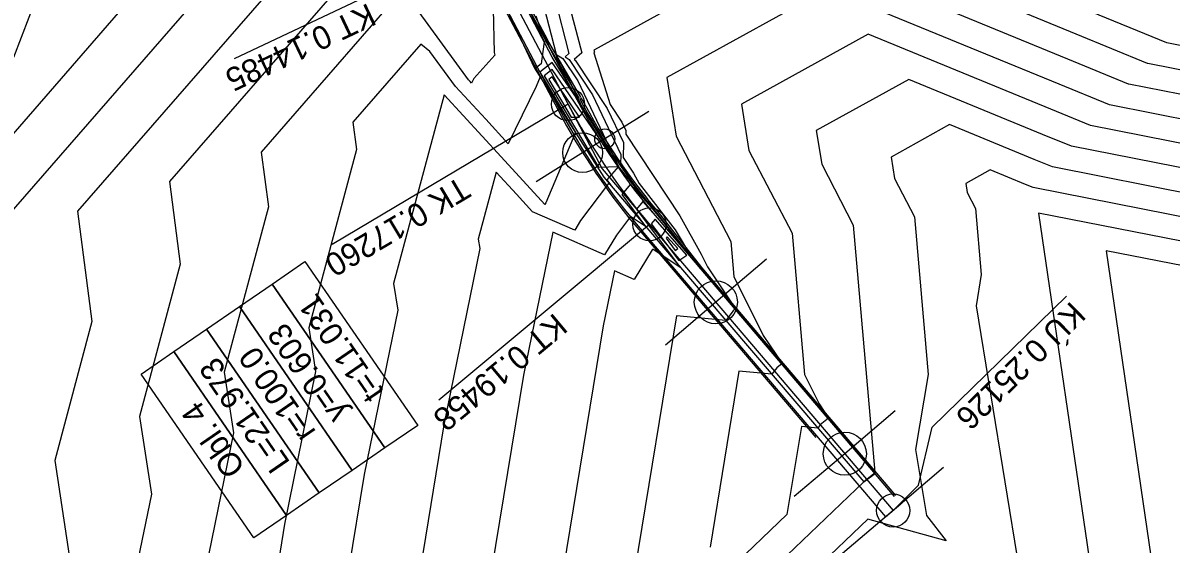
# Model space of a CAD drawing. Extents: x -549394 to -546608, y -1037055 to -1033629.
# Drawn here: x -547510.8 to -547337.6, y -1036070.9 to -1035992.3 of the extents above; entities that cross this region are included whole.
import ezdxf

# ---------------------------------------------------------------- set-up
doc = ezdxf.new("R2010")
doc.units = 0
for name, color, linetype in [('hlavni_vrst', 7, 'Continuous'), ('hrana_L', 7, 'Continuous'), ('norm_vrst', 7, 'Continuous'), ('POLYGONY_SITUACE_PO', 7, 'Continuous'), ('u_sirka_1_5m', 7, 'Continuous'), ('x_navrh_C41', 7, 'Continuous'), ('x_osa_C41', 7, 'Continuous'), ('x_popis_oblouky_C41', 7, 'Continuous'), ('x_popis_pricne_rezy_C41', 7, 'Continuous')]:
    doc.layers.add(name, color=color, linetype=linetype)

msp = doc.modelspace()

# ---------------------------------------------------------------- linework, layer by layer
at = {"layer": 'hlavni_vrst'}
for p, q in [((-547457.55, -1035980.45), (-547488.68, -1036016.25)), ((-547432.72, -1035980.4), (-547428.42, -1035996.91)), ((-547338.28, -1035995.31), (-547350.68, -1035990.21)), ((-547338.27, -1035995.32), (-547338.28, -1035995.31)), ((-547253.9, -1036011.93), (-547338.27, -1035995.32)), ((-547428.42, -1035996.91), (-547429.01, -1035997.44)), ((-547429.01, -1035997.44), (-547428.4, -1035997.81)), ((-547428.4, -1035997.81), (-547424.88, -1036003.14)), ((-547430.97, -1036000.44), (-547431.46, -1036000.82)), ((-547431.46, -1036000.82), (-547428.07, -1036006.54)), ((-547426.82, -1036006.5), (-547430.97, -1036000.44)), ((-547377.16, -1036000.82), (-547391.13, -1036008.54)), ((-547357.02, -1036009.12), (-547377.16, -1036000.82)), ((-547424.88, -1036003.14), (-547420.59, -1036012.16)), ((-547428.07, -1036006.54), (-547426.82, -1036006.5)), ((-547391.13, -1036008.54), (-547390.31, -1036013.64)), ((-547352.65, -1036010.91), (-547357.02, -1036009.12)), ((-547352.65, -1036010.92), (-547352.65, -1036010.91)), ((-547248.01, -1036031.52), (-547352.65, -1036010.92)), ((-547420.59, -1036012.16), (-547420.63, -1036013.66)), ((-547420.63, -1036013.66), (-547416.7, -1036018.73)), ((-547390.31, -1036013.64), (-547385.56, -1036022.8)), ((-547488.68, -1036016.25), (-547487.05, -1036028.71)), ((-547419.13, -1036016.61), (-547420.47, -1036018.2)), ((-547415.54, -1036020.67), (-547419.13, -1036016.61)), ((-547420.47, -1036018.2), (-547416.86, -1036023)), ((-547416.7, -1036018.73), (-547415.54, -1036020.67)), ((-547419.13, -1036021.5), (-547421.27, -1036024.34)), ((-547416.86, -1036023), (-547419.13, -1036021.5)), ((-547430.88, -1036023.9), (-547435.28, -1036045.47)), ((-547423.07, -1036027.31), (-547430.88, -1036023.9)), ((-547385.56, -1036022.8), (-547382.3, -1036060.1)), ((-547421.27, -1036024.34), (-547423.07, -1036027.31)), ((-547487.05, -1036028.71), (-547493.18, -1036051.67)), ((-547435.28, -1036045.47), (-547441.94, -1036086.16)), ((-547493.18, -1036051.67), (-547491.39, -1036063.41)), ((-547382.26, -1036060.17), (-547383.95, -1036061.55)), ((-547382.3, -1036060.1), (-547382.27, -1036060.15)), ((-547382.27, -1036060.15), (-547382.26, -1036060.17)), ((-547383.95, -1036061.55), (-547529.34, -1036200.56)), ((-547383.95, -1036061.55), (-547383.95, -1036061.55)), ((-547383.95, -1036061.55), (-547383.95, -1036061.55)), ((-547383.95, -1036061.55), (-547383.95, -1036061.55)), ((-547383.95, -1036061.55), (-547383.95, -1036061.55)), ((-547383.95, -1036061.55), (-547383.95, -1036061.55)), ((-547383.95, -1036061.55), (-547383.95, -1036061.55)), ((-547383.95, -1036061.55), (-547383.95, -1036061.55)), ((-547491.39, -1036063.41), (-547495.36, -1036082.87))]:
    msp.add_line(p, q, dxfattribs=at)
at = {"layer": 'hrana_L'}
for p, q in [((-547443.92, -1035977.28), (-547433.62, -1035999.11)), ((-547430.95, -1035997.46), (-547441.95, -1035976.42)), ((-547420.97, -1036013.96), (-547430.95, -1035997.46)), ((-547433.62, -1035999.11), (-547423.14, -1036015.56)), ((-547409.46, -1036028.18), (-547420.97, -1036013.96)), ((-547423.14, -1036015.56), (-547411.32, -1036029.57)), ((-547382.19, -1036060.25), (-547409.46, -1036028.18)), ((-547411.32, -1036029.57), (-547383.95, -1036061.55)), ((-547383.95, -1036061.55), (-547382.19, -1036060.25))]:
    msp.add_line(p, q, dxfattribs=at)
at = {"layer": 'norm_vrst'}
for p, q in [((-547497.77, -1035960.08), (-547512.2, -1035997.51)), ((-547460.95, -1035972.91), (-547502.52, -1036020.73)), ((-547436.76, -1035972.39), (-547430.35, -1035997)), ((-547351.95, -1035993.99), (-547401.7, -1035973.51)), ((-547477.28, -1035980.25), (-547516.37, -1036025.2)), ((-547395.57, -1035980.34), (-547424.56, -1035996.36)), ((-547353.22, -1035997.77), (-547395.57, -1035980.34)), ((-547435.78, -1035987.5), (-547432.13, -1035995.21)), ((-547389.43, -1035987.17), (-547413.67, -1036000.56)), ((-547354.49, -1036001.55), (-547389.43, -1035987.17)), ((-547494.74, -1035988.88), (-547530.21, -1036029.67)), ((-547454.15, -1035987.99), (-547474.83, -1036011.78)), ((-547428.69, -1035988.4), (-547426.49, -1035996.82)), ((-547443.56, -1036000.88), (-547451.39, -1035990.15)), ((-547439.87, -1035990.21), (-547439.71, -1035996.78)), ((-547433.43, -1035991.22), (-547433.03, -1035992.43)), ((-547433.03, -1035992.43), (-547430.74, -1035997.26)), ((-547383.29, -1035993.99), (-547402.4, -1036004.55)), ((-547355.75, -1036005.34), (-547383.29, -1035993.99)), ((-547341.16, -1035998.43), (-547351.95, -1035993.99)), ((-547450.75, -1035995.53), (-547460.99, -1036007.3)), ((-547449.39, -1035996.6), (-547450.75, -1035995.53)), ((-547432.2, -1035995.52), (-547432.63, -1035998.5)), ((-547432.13, -1035995.21), (-547432.2, -1035995.52)), ((-547424.56, -1035996.36), (-547424.65, -1035996.41)), ((-547424.65, -1035996.41), (-547424.57, -1035996.73)), ((-547445.51, -1036001.91), (-547449.39, -1035996.6)), ((-547439.62, -1035997.19), (-547442.79, -1036000.71)), ((-547439.71, -1035996.78), (-547439.62, -1035997.19)), ((-547430.74, -1035997.26), (-547430.27, -1035997.55)), ((-547430.35, -1035997), (-547430.38, -1035997.04)), ((-547430.38, -1035997.04), (-547429.33, -1035997.68)), ((-547430.27, -1035997.55), (-547429.33, -1035998.98)), ((-547429.33, -1035997.68), (-547427.1, -1036001.06)), ((-547426.49, -1035996.82), (-547427.63, -1035997.83)), ((-547427.63, -1035997.83), (-547427.47, -1035997.93)), ((-547427.47, -1035997.93), (-547422.66, -1036005.22)), ((-547424.57, -1035996.73), (-547424.65, -1035996.8)), ((-547424.65, -1035996.8), (-547422.21, -1036004.6)), ((-547344.03, -1036001.55), (-547353.22, -1035997.77)), ((-547432.63, -1035998.5), (-547433.51, -1035999.2)), ((-547433.51, -1035999.2), (-547432.76, -1036000.45)), ((-547430.96, -1035998.26), (-547432.83, -1035999.74)), ((-547432.83, -1035999.74), (-547427.42, -1036008.85)), ((-547430.97, -1035999.35), (-547432.15, -1036000.28)), ((-547420.97, -1036013.96), (-547430.97, -1035999.35)), ((-547426.74, -1036004.42), (-547430.96, -1035998.26)), ((-547429.33, -1035998.98), (-547426.74, -1036004.42)), ((-547341.15, -1035998.44), (-547341.16, -1035998.43)), ((-547252.72, -1036015.85), (-547341.15, -1035998.44)), ((-547443.3, -1036001.16), (-547443.56, -1036000.88)), ((-547443.11, -1036001.37), (-547443.3, -1036001.16)), ((-547442.79, -1036000.71), (-547443.11, -1036001.37)), ((-547432.76, -1036000.45), (-547433.39, -1036001.91)), ((-547432.15, -1036000.28), (-547423.96, -1036014.06)), ((-547427.1, -1036001.06), (-547420.97, -1036013.96)), ((-547413.67, -1036000.56), (-547412.26, -1036009.41)), ((-547346.9, -1036004.67), (-547354.49, -1036001.55)), ((-547344.02, -1036001.56), (-547344.03, -1036001.55)), ((-547251.54, -1036019.77), (-547344.02, -1036001.56)), ((-547447.26, -1036003.15), (-547454.86, -1036031.63)), ((-547438.66, -1036012.49), (-547447.26, -1036003.15)), ((-547440.98, -1036006.82), (-547445.51, -1036001.91)), ((-547433.39, -1036001.91), (-547437.58, -1036010.53)), ((-547422.21, -1036004.6), (-547420.43, -1036007.3)), ((-547402.4, -1036004.55), (-547401.29, -1036011.53)), ((-547346.9, -1036004.68), (-547346.9, -1036004.67)), ((-547250.37, -1036023.69), (-547346.9, -1036004.68)), ((-547437.58, -1036010.53), (-547440.98, -1036006.82)), ((-547422.66, -1036005.22), (-547420.22, -1036010.35)), ((-547349.78, -1036007.79), (-547355.75, -1036005.34)), ((-547460.99, -1036007.3), (-547460.45, -1036011.4)), ((-547420.43, -1036007.3), (-547419.84, -1036008.55)), ((-547419.84, -1036008.55), (-547419.85, -1036009.09)), ((-547371.02, -1036007.65), (-547379.86, -1036012.54)), ((-547358.29, -1036012.9), (-547371.02, -1036007.65)), ((-547349.77, -1036007.8), (-547349.78, -1036007.79)), ((-547249.19, -1036027.6), (-547349.77, -1036007.8)), ((-547427.42, -1036008.85), (-547431.93, -1036019.44)), ((-547419.85, -1036009.09), (-547411.72, -1036021.41)), ((-547412.26, -1036009.41), (-547404.01, -1036025.3)), ((-547474.83, -1036011.78), (-547473.75, -1036020.05)), ((-547460.45, -1036011.4), (-547467.63, -1036038.31)), ((-547420.22, -1036010.35), (-547420.27, -1036012.6)), ((-547401.29, -1036011.53), (-547394.78, -1036024.05)), ((-547432.06, -1036019.7), (-547438.66, -1036012.49)), ((-547420.27, -1036012.6), (-547418.7, -1036014.98)), ((-547379.86, -1036012.54), (-547379.34, -1036015.76)), ((-547355.53, -1036014.03), (-547358.29, -1036012.9)), ((-547439.39, -1036014.84), (-547442.09, -1036024.94)), ((-547436.34, -1036018.15), (-547439.39, -1036014.84)), ((-547423.96, -1036014.06), (-547420.97, -1036013.96)), ((-547420.97, -1036013.96), (-547422.69, -1036016)), ((-547420.97, -1036013.96), (-547420.97, -1036013.96)), ((-547420.97, -1036013.96), (-547420.97, -1036013.96)), ((-547420.97, -1036013.96), (-547420.97, -1036013.96)), ((-547420.97, -1036013.96), (-547420.97, -1036013.96)), ((-547418.7, -1036014.98), (-547417.82, -1036016.55)), ((-547364.89, -1036014.48), (-547368.59, -1036016.53)), ((-547359.56, -1036016.68), (-547364.89, -1036014.48)), ((-547355.52, -1036014.04), (-547355.53, -1036014.03)), ((-547246.84, -1036035.44), (-547355.52, -1036014.04)), ((-547422.47, -1036016.55), (-547426.66, -1036022.12)), ((-547422.69, -1036016), (-547422.09, -1036016.8)), ((-547422.09, -1036016.8), (-547422.47, -1036016.55)), ((-547417.82, -1036016.55), (-547412.43, -1036023.5)), ((-547379.34, -1036015.76), (-547376.33, -1036021.55)), ((-547368.59, -1036016.53), (-547368.37, -1036017.88)), ((-547358.4, -1036017.15), (-547359.56, -1036016.68)), ((-547358.4, -1036017.15), (-547358.4, -1036017.15)), ((-547245.66, -1036039.35), (-547358.4, -1036017.15)), ((-547433.91, -1036020.8), (-547436.34, -1036018.15)), ((-547368.37, -1036017.88), (-547367.11, -1036020.3)), ((-547473.75, -1036020.05), (-547480.4, -1036044.99)), ((-547431.93, -1036019.44), (-547432.06, -1036019.7)), ((-547417.28, -1036019.27), (-547418.24, -1036020.4)), ((-547418.24, -1036020.4), (-547411.63, -1036029.2)), ((-547410.11, -1036027.38), (-547417.28, -1036019.27)), ((-547367.11, -1036020.3), (-547366.24, -1036030.25)), ((-547502.52, -1036020.73), (-547500.35, -1036037.36)), ((-547427.55, -1036023.59), (-547433.91, -1036020.8)), ((-547426.66, -1036022.12), (-547427.55, -1036023.59)), ((-547415.44, -1036021.92), (-547416.01, -1036022.6)), ((-547410.66, -1036027.33), (-547415.44, -1036021.92)), ((-547411.72, -1036021.41), (-547408.48, -1036027.21)), ((-547376.33, -1036021.55), (-547374.26, -1036045.33)), ((-547357.62, -1036020.99), (-547348.49, -1036083.4)), ((-547244.48, -1036043.27), (-547357.62, -1036020.99)), ((-547416.01, -1036022.6), (-547411.85, -1036028.14)), ((-547412.43, -1036023.5), (-547410.11, -1036027.38)), ((-547394.78, -1036024.05), (-547392.92, -1036045.34)), ((-547442.09, -1036024.94), (-547441.87, -1036026.36)), ((-547413.59, -1036024.58), (-547413.78, -1036024.8)), ((-547413.78, -1036024.8), (-547412.41, -1036026.62)), ((-547412.02, -1036026.36), (-547413.59, -1036024.58)), ((-547404.01, -1036025.3), (-547403.54, -1036030.58)), ((-547441.87, -1036026.36), (-547447.29, -1036052.95)), ((-547415.88, -1036026.56), (-547418.59, -1036031.04)), ((-547415.79, -1036026.45), (-547415.88, -1036026.56)), ((-547411.63, -1036029.2), (-547415.79, -1036026.45)), ((-547412.41, -1036026.62), (-547412.02, -1036026.36)), ((-547411.85, -1036028.14), (-547410.66, -1036027.33)), ((-547408.48, -1036027.21), (-547407.54, -1036029.1)), ((-547347.44, -1036026.68), (-547339.04, -1036084.12)), ((-547243.31, -1036047.19), (-547347.44, -1036026.68)), ((-547407.54, -1036029.1), (-547403.29, -1036035.43)), ((-547421.58, -1036029.73), (-547423.26, -1036037.99)), ((-547418.59, -1036031.04), (-547421.58, -1036029.73)), ((-547403.54, -1036030.58), (-547399.12, -1036039.45)), ((-547366.24, -1036030.25), (-547367.03, -1036035)), ((-547454.86, -1036031.63), (-547454.25, -1036035.63)), ((-547454.25, -1036035.63), (-547459.31, -1036060.43)), ((-547403.67, -1036035.75), (-547404.79, -1036037.2)), ((-547403.29, -1036035.43), (-547403.67, -1036035.75)), ((-547367.03, -1036035), (-547359.98, -1036078.3)), ((-547500.35, -1036037.36), (-547505.95, -1036058.35)), ((-547423.26, -1036037.99), (-547430.34, -1036081.24)), ((-547412.23, -1036036.52), (-547418.74, -1036076.32)), ((-547404.79, -1036037.2), (-547412.23, -1036036.52)), ((-547467.63, -1036038.31), (-547466.63, -1036044.89)), ((-547399.12, -1036039.45), (-547396.28, -1036043.68)), ((-547466.63, -1036044.89), (-547471.32, -1036067.91)), ((-547402.8, -1036044.86), (-547407.14, -1036071.39)), ((-547397.84, -1036045.32), (-547402.8, -1036044.86)), ((-547397.1, -1036044.35), (-547397.84, -1036045.32)), ((-547396.28, -1036043.68), (-547397.1, -1036044.35)), ((-547480.4, -1036044.99), (-547479.01, -1036054.15)), ((-547392.92, -1036045.34), (-547390.7, -1036049.8)), ((-547374.26, -1036045.33), (-547376.15, -1036056.66)), ((-547390.7, -1036049.8), (-547389.27, -1036051.92)), ((-547447.29, -1036052.95), (-547453.53, -1036091.08)), ((-547393.38, -1036053.21), (-547395.55, -1036066.47)), ((-547390.9, -1036053.43), (-547393.38, -1036053.21)), ((-547390.52, -1036052.95), (-547390.9, -1036053.43)), ((-547389.27, -1036051.92), (-547390.52, -1036052.95)), ((-547479.01, -1036054.15), (-547483.34, -1036075.39)), ((-547376.15, -1036056.66), (-547374.52, -1036066.65)), ((-547505.95, -1036058.35), (-547503.77, -1036072.68)), ((-547459.31, -1036060.43), (-547465.13, -1036096)), ((-547395.55, -1036066.47), (-547533.98, -1036198.84)), ((-547383.37, -1036067.17), (-547524.69, -1036202.29)), ((-547371.54, -1036070.47), (-547383.37, -1036067.17)), ((-547374.52, -1036066.65), (-547371.54, -1036070.47)), ((-547471.32, -1036067.91), (-547476.73, -1036100.93))]:
    msp.add_line(p, q, dxfattribs=at)
at = {"layer": 'POLYGONY_SITUACE_PO'}
for centre in [(-547428.56, -1036004.55), (-547416.27, -1036022.7), (-547379.53, -1036065.87)]:
    msp.add_circle(centre, 2.5, dxfattribs=at)
at = {"layer": 'u_sirka_1_5m'}
for centre, radius in [((-547423.03, -1036009.8), 1.5), ((-547426.36, -1036011.88), 3), ((-547406.27, -1036034.45), 3.25), ((-547386.83, -1036057.3), 3.25)]:
    msp.add_circle(centre, radius, dxfattribs=at)
at = {"layer": 'x_navrh_C41'}
for p, q in [((-547443.06, -1035980.82), (-547430.11, -1036005.36)), ((-547442.84, -1035980.7), (-547429.89, -1036005.25)), ((-547440.18, -1035979.3), (-547427.24, -1036003.85)), ((-547441.1, -1035984.52), (-547430.11, -1036005.36)), ((-547435.29, -1035988.04), (-547431.68, -1035994.88)), ((-547426.86, -1036003.65), (-547431.9, -1035995)), ((-547426.64, -1036003.52), (-547431.68, -1035994.88)), ((-547415.13, -1036021.73), (-547379.37, -1036063.75)), ((-547414.8, -1036021.45), (-547408.65, -1036029.35)), ((-547414.6, -1036021.3), (-547408.45, -1036029.19)), ((-547417.6, -1036023.84), (-547391.2, -1036054.87)), ((-547417.41, -1036023.68), (-547380.68, -1036066.85)), ((-547408.45, -1036029.19), (-547379.18, -1036063.59)), ((-547380.68, -1036066.85), (-547378.37, -1036064.89))]:
    msp.add_line(p, q, dxfattribs=at)
for radius in [98.5, 98.07, 97.82, 101.75, 101.5]:
    msp.add_arc((-547340.11, -1035957.9), radius, 207.8077, 220.3973, dxfattribs=at)
at = {"layer": 'x_osa_C41'}
for points in [[(-547453.65, -1035956.98), (-547423.42, -1036014.3)], [(-547423.42, -1036014.3), (-547379.53, -1036065.87)]]:
    msp.add_lwpolyline(points, dxfattribs=at)
msp.add_arc((-547340.11, -1035957.9), 100, 207.8077, 220.3973, dxfattribs=at)
at = {"layer": 'x_popis_oblouky_C41'}
msp.add_line((-547379.53, -1036065.87), (-547375.72, -1036062.04), dxfattribs=at)
for points in [[(-547441.51, -1035980), (-547478.9, -1035997.71)], [(-547428.56, -1036004.55), (-547464.11, -1036025.73)], [(-547416.27, -1036022.7), (-547448.05, -1036049.2)], [(-547379.53, -1036065.87), (-547375.72, -1036062.04), (-547373.66, -1036053.28), (-547353.39, -1036033.54)]]:
    msp.add_lwpolyline(points, dxfattribs=at)
for points in [[(-547456.18, -1036056.43), (-547473.17, -1036031.71), (-547468.23, -1036028.31), (-547451.23, -1036053.03)], [(-547461.12, -1036059.83), (-547478.12, -1036035.1), (-547473.17, -1036031.71), (-547456.18, -1036056.43)], [(-547466.07, -1036063.23), (-547483.06, -1036038.5), (-547478.12, -1036035.1), (-547461.12, -1036059.83)], [(-547471.01, -1036066.62), (-547488.01, -1036041.9), (-547483.06, -1036038.5), (-547466.07, -1036063.23)], [(-547475.96, -1036070.02), (-547492.95, -1036045.3), (-547488.01, -1036041.9), (-547471.01, -1036066.62)]]:
    msp.add_lwpolyline(points, close=True, dxfattribs=at)
at = {"layer": 'x_popis_pricne_rezy_C41'}
for points in [[(-547416.4, -1036005.65), (-547424.88, -1036010.95), (-547433.35, -1036016.26)], [(-547398.66, -1036027.97), (-547406.27, -1036034.45), (-547413.89, -1036040.93)], [(-547379.22, -1036050.82), (-547386.83, -1036057.3), (-547394.45, -1036063.78)], [(-547371.92, -1036059.39), (-547379.53, -1036065.87), (-547387.15, -1036072.35)]]:
    msp.add_lwpolyline(points, dxfattribs=at)

# ---------------------------------------------------------------- texts
at = {"layer": 'x_popis_oblouky_C41'}
for s, rotation, p in [('KT 0.14485', 205.3483, (-547458.7, -1035989.24)), ('TK 0.17260', 210.7904, (-547444.77, -1036015.36)), ('t=11.031', 124.5304, (-547456.16, -1036047.99)), ('KÚ 0.25126', 224.3937, (-547352.68, -1036034.17)), ('KT 0.19458', 219.8171, (-547430.6, -1036035.95)), ('y=0.603', 124.5304, (-547461.7, -1036051.14)), ('r=100.0', 124.5304, (-547466.48, -1036054)), ('L=21.973', 124.5304, (-547470.36, -1036058.65)), ('Obl. 4', 124.5304, (-547477.12, -1036059.4))]:
    msp.add_text(s, height=3.5, rotation=rotation, dxfattribs=at).set_placement(p)

doc.saveas('drawing.dxf')
